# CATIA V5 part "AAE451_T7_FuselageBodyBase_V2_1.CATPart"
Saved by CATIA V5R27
Part number: FB1
Bounding box of the stored display mesh (mm): x -98.432 to 98.432, y -250 to -100, z -67 to 0
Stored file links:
  W:\AAE 451\AAE451_T7_FuselageAssemble_V2\AAE451_T7_FuselageAssemble_V2\AAE451_T7_FuselageBodyBase_V2_1.CATPart
  W:\AAE 451\AAE451_T7_FuselageBody.CATPart
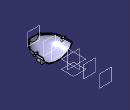
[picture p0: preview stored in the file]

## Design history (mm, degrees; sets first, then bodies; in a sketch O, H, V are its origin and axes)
Body1 (main body)
Body2
  Plane1: type Offset, RefPlane zx-plane, Offset 250, reversed
  Plane2: type Offset, RefPlane zx-plane, Offset 100
  Sketch1 on Plane1, origin (0, -250, 0), H (-1, 0, 0), V (0, 0, 1)
    circle A1 centre (0, 0) radius 30
    distance O A1 = 30
  Plane3: type Offset, RefPlane zx-plane, Offset 150, reversed
  Sketch2 on Plane2, origin (0, 100, 0), H (-1, 0, 0), V (0, 0, 1)
    construction line L1 (0, 60) -> (0, -40)
    point P1 (0, 60)
    construction line L2 (-92.2886, 30) -> (87.7114, 30)
    point P5 (0, 30)
    coincidence: P1 V, P5 L2, P5 L1
    vertical: L1 V
    horizontal: L2 H
  Sketch3 on Plane2, origin (0, 100, 0), H (-1, 0, 0), V (0, 0, 1)
    construction line L1 (0, -100) -> (0, 70)
    point P1 (0, -100)
    construction line L2 (-103.4986, 30) -> (116.5014, 30)
    point P5 (0, 30)
    point P6 (0, 60)
    construction line L3 (-60, 60) -> (60, 60)
    point P7 (-60, 60)
    reference projected curve E1 from Sketch4.E1
    ellipse A1 centre (0, 60) semi-axes 60, 35 rotation 180 from (-60, 60) to (60, 60)
    point P8 (-60, 60)
    point P9 (60, 60)
    point P10 (60, 60)
    point P11 (-60, 60)
    ellipse A2 centre (0, 60) semi-axes 60, 35 rotation 180 from (-60, 60) to (60, 60)
    "Radius" A1 = 60
    "Radius" A1 = 35
    coincidence: P1 V, P5 L2, P5 L1, P6 L1, A1 P7, P7 L3, P6 L3
    vertical: L1 V
    horizontal: L2 H, L3 H, A1 H
    tangency: L3 E1
    symmetry: P9 P10 L3, P8 P11 L3, A1 A2 L3
  Sketch4 on zx-plane, origin (0, 0, 0), H (-1, 0, 0), V (0, 0, 1)
    projected curve E1 from Sketch5.A1
  Sketch5 on Plane3, origin (0, -150, 0), H (-1, 0, 0), V (0, 0, 1)
    construction line L1 (50, 50) -> (50, -50)
    construction line L2 (50, -50) -> (-50, -50)
    construction line L3 (-50, -50) -> (-50, 50)
    construction line L4 (-50, 50) -> (50, 50)
    point P1 (50, 50)
    point P2 (50, -50)
    point P3 (-50, -50)
    point P4 (-50, 50)
    construction line L5 (0, -60) -> (0, 90)
    point P5 (0, -60)
    construction line L6 (-100, 0) -> (110, 0)
    point P7 (-100, 0)
    ellipse A1 centre (0, 0) semi-axes 90.4534, 60 rotation 0
    point P9 (0, 60)
    length L1 = 100
    length L4 = 100
    vertical: L1 V, L3 V, L5 V
    horizontal: L2 H, L4 H, L6 H, A1 H
    equidistance: L1 L3 O, L2 L4 O
    coincidence: P5 V, P7 H, P9 L5, A1 P9, P2 A1, A1 P3, P1 A1, P4 A1
    parallelism: A1 L6
  Loft1: solid, Sections (Sketch3; Sketch4; Sketch5; Sketch1)
  Sketch6 on face of Loft1, origin (0, 100, 0), H (-1, 0, 0), V (0, 0, 1)
    line L1 (-70, 95) -> (70, 95)
    line L2 (70, 95) -> (70, 60)
    line L3 (70, 60) -> (-70, 60)
    line L4 (-70, 60) -> (-70, 95)
    reference projected curve E1 from edge [face of Loft1 | face of Loft1]
    construction line L5 (-60, 60) -> (60, 60)
    length L1 = 140
    horizontal: L1 H, L3 H, L5 H
    vertical: L2 V, L4 V
    coincidence: L3 L5
    tangency: L1 E1
    symmetry: L4 L2 V
  Pocket1: profile Sketch6, direction (0, -1, 0), through (limit type 6)
  Plane4: type Offset, RefPlane Plane2, Offset 100
  Sketch7 on Plane4, origin (0, 200, 0), H (-1, 0, 0), V (0, 0, 1)
    projected line E2 (-60, 60) -> (60, 60) from edge [face of Loft1 | face of Pocket1 from Sketch6.L3]
  Pad1: profile Sketch7, direction (0, 1, 0), up to the existing solid (limit type 3)
  Sketch8 on face of Loft1, origin (0, -250, 0), H (1, 0, 0), V (0, 0, 1)
    line L1 (-97.5192, 0) -> (97.5192, 0)
    point P1 (-97.5192, 0)
    point P2 (97.5192, 0)
    projected line E1 (-62.8781, 60) -> (63.056, 60) from edge [face of Loft1 | face of Pad1]
    line L2 (-97.5192, 0) -> (-62.8781, 60)
    line L3 (97.5192, 0) -> (63.056, 60)
    angle L1 L2 = 60
    horizontal: L1 H
    symmetry: P1 P2 V
    coincidence: H L1
  Pocket2: profile Sketch8, direction (0, 1, 0), through (limit type 3)
  Shell1: ExtOffset 0, Face face of Pocket2 from Sketch8.L1, IntOffset 4
  Sketch9 on face of Pocket2 from Sketch8.L1, origin (0, 0, 0), H (1, 0, 0), V (0, 1, 0)
    arc A1 centre (93.4423, -150) radius 5 from (93.4423, -155) to (93.4423, -145) ccw
    point P1 (93.4423, -150)
    line L1 (93.4423, -145) -> (86.4534, -145)
    point P2 (86.4534, -145)
    line L2 (93.4423, -155) -> (86.4312, -155)
    point P3 (86.4312, -155)
    reference projected curve E1 from edge [face of Pocket2 from Sketch8.L1 | face of Shell1]
    reference projected curve E2 from edge [face of Shell1 | face of Pocket2 from Sketch8.L1]
    reference intersected line E3 through (0, -150) direction (-1, 0) from Plane3
    line L3 (86.4534, -145) -> (86.4312, -155)
    distance L1 L2 = 10
    distance L3 P1 = 7
    horizontal: L1 H, L2 H
    tangency: L1 A1, L2 A1
    coincidence: P3 E1, P2 E2, E3 P1
  Pad2: profile Sketch9, direction (0, 0, -1), length 10
  RectPattern1: of Pad2, direction 1 instances 3, spacing 75, along yz-plane
  Mirror1: of RectPattern1, about yz-plane
  Plane5: type Offset, RefPlane xy-plane, Offset 55, reversed
  Sketch10 on Plane5, origin (0, 0, -55), H (1, 0, 0), V (0, 1, 0)
    line L1 (67.5, -137.75) -> (-67.5, -137.75)
    line L2 (-67.5, -137.75) -> (-67.5, -162.25)
    line L3 (-67.5, -162.25) -> (67.5, -162.25)
    line L4 (67.5, -162.25) -> (67.5, -137.75)
    construction line L5 (132.2933, -150) -> (-145.9619, -150)
    distance L4 L2 = 135
    length L2 = 24.5
    distance L5 H = 150
    horizontal: L1 H, L3 H
    vertical: L2 V, L4 V
    symmetry: L4 L2 V, L1 L3 L5
  Pad3: profile Sketch10, direction (0, 0, -1), length 12, opposite side up to the existing solid (limit type 2)
  Fillet1: radius 10, on edge [end face of Pad3 | face of Pad3 from Sketch10.L4]; edge [end face of Pad3 | face of Pad3 from Sketch10.L2]
  Sketch11 on face of RectPattern1, origin (0, 0, 0), H (1, 0, 0), V (0, 1, 0)
    circle A1 centre (93.4423, -150) radius 2.5
    reference projected arc E1 centre (93.4423, -150) radius 5 from (93.4423, -155) to (93.4423, -145) ccw from edge [face of Pad2 from Sketch9.A1 | face of RectPattern1]
    radius A1 = 2.5
    concentricity: A1 E1
  Pocket3: profile Sketch11, direction (0, 0, -1), through (limit type 3)
  RectPattern2: of Pocket3, direction 1 instances 3, spacing 75, along yz-plane
  Mirror2: of RectPattern2, about yz-plane
  Plane6 "PRINT CAPACITY": type Offset, RefPlane Plane1, Offset 150
  Sketch12 on Plane6, origin (0, -100, 0), H (-1, 0, 0), V (0, 0, 1)
    point P1 (-2.7383, -33.5)
    line L1 (146.5133, 0) -> (146.5133, -67)
    line L2 (146.5133, -67) -> (-151.9899, -67)
    line L3 (-151.9899, -67) -> (-151.9899, 0)
    line L4 (-151.9899, 0) -> (146.5133, 0)
    reference projected line E1 (-67.5, -67) -> (67.5, -67) from edge [end face of Pad3 | face of Pad3 from Sketch10.L1]
    vertical: L1 V, L3 V
    horizontal: L2 H, L4 H
    equidistance: L1 L3 P1, L2 L4 P1
    coincidence: L4 H, L2 E1
  Pocket4: profile Sketch12, direction (0, 1, 0), through (limit type 3)
  Sketch13 on end face of Pad3, origin (0, 0, -67), H (1, 0, 0), V (0, -1, 0)
    circle A1 centre (-37, 150) radius 2.972
    point P1 (-37, 150)
    reference projected line E1 (-67.5, 162.25) -> (67.5, 162.25) from edge [end face of Pad3 | face of Pad3 from Sketch10.L3]
    reference projected line E2 (67.5, 137.75) -> (-67.5, 137.75) from edge [end face of Pad3 | face of Pad3 from Sketch10.L1]
    circle A2 centre (37, 150) radius 2.972
    radius A1 = 2.972
    distance P1 V = 37
    equidistance: E1 E2 P1
    symmetry: A1 A2 V
  Pocket5: profile Sketch13, direction (0, 0, 1), length 7.79
  Sketch14 on face of RectPattern1, origin (0, 0, 0), H (1, 0, 0), V (0, 1, 0)
    arc A1 centre (-76.4423, -150) radius 5 from (-76.4423, -155) to (-76.4423, -145) ccw
    point P1 (-76.4423, -150)
    line L1 (-86.4534, -145) -> (-76.4423, -145)
    point P2 (-86.4534, -145)
    line L2 (-86.4312, -155) -> (-76.4423, -155)
    point P3 (-86.4312, -155)
    reference projected line E1 (-86.4534, -145) -> (-86.4312, -155) from edge [face of RectPattern1 | face of Mirror1]
    reference projected line E2 (-86.4534, -145) -> (-86.4312, -155) from edge [face of RectPattern1 | face of Mirror1]
    line L3 (-86.4312, -155) -> (-86.4534, -145)
    construction line L4 (-93.4423, -150) -> (-76.4423, -150)
    point P4 (-93.4423, -150)
    reference projected circle E3 centre (-93.4423, -150) radius 2.5 from edge [face of Mirror2 | face of RectPattern1]
    radius A1 = 5
    distance P1 L3 = 10
    horizontal: L1 H, L2 H, L4 H
    coincidence: P3 E1, P2 E2
    concentricity: P4 E3
    tangency: L1 A1, L2 A1
  Pad4: profile Sketch14, direction (0, 0, -1), length 13
  Sketch15 on face of Pad4, origin (-76.5818, -149.4637, 0), H (1, 0, 0), V (0, 1, 0)
    point P1 (0.1395, -0.5363)
    reference projected arc E1 centre (0.1395, -0.5363) radius 5 from (0.1395, -5.5363) to (0.1395, 4.4637) ccw from edge [face of Pad4 from Sketch14.A1 | start face of Pad4]
    concentricity: P1 E1
  Hole1: placed by Sketch15, at (-76.4423, -150, 0) direction (0, 0, -1), diameter 4.5, through (limit type 6), countersink depth 7.9, countersink angle 8
  Mirror3: of Pad4, Hole1, about yz-plane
